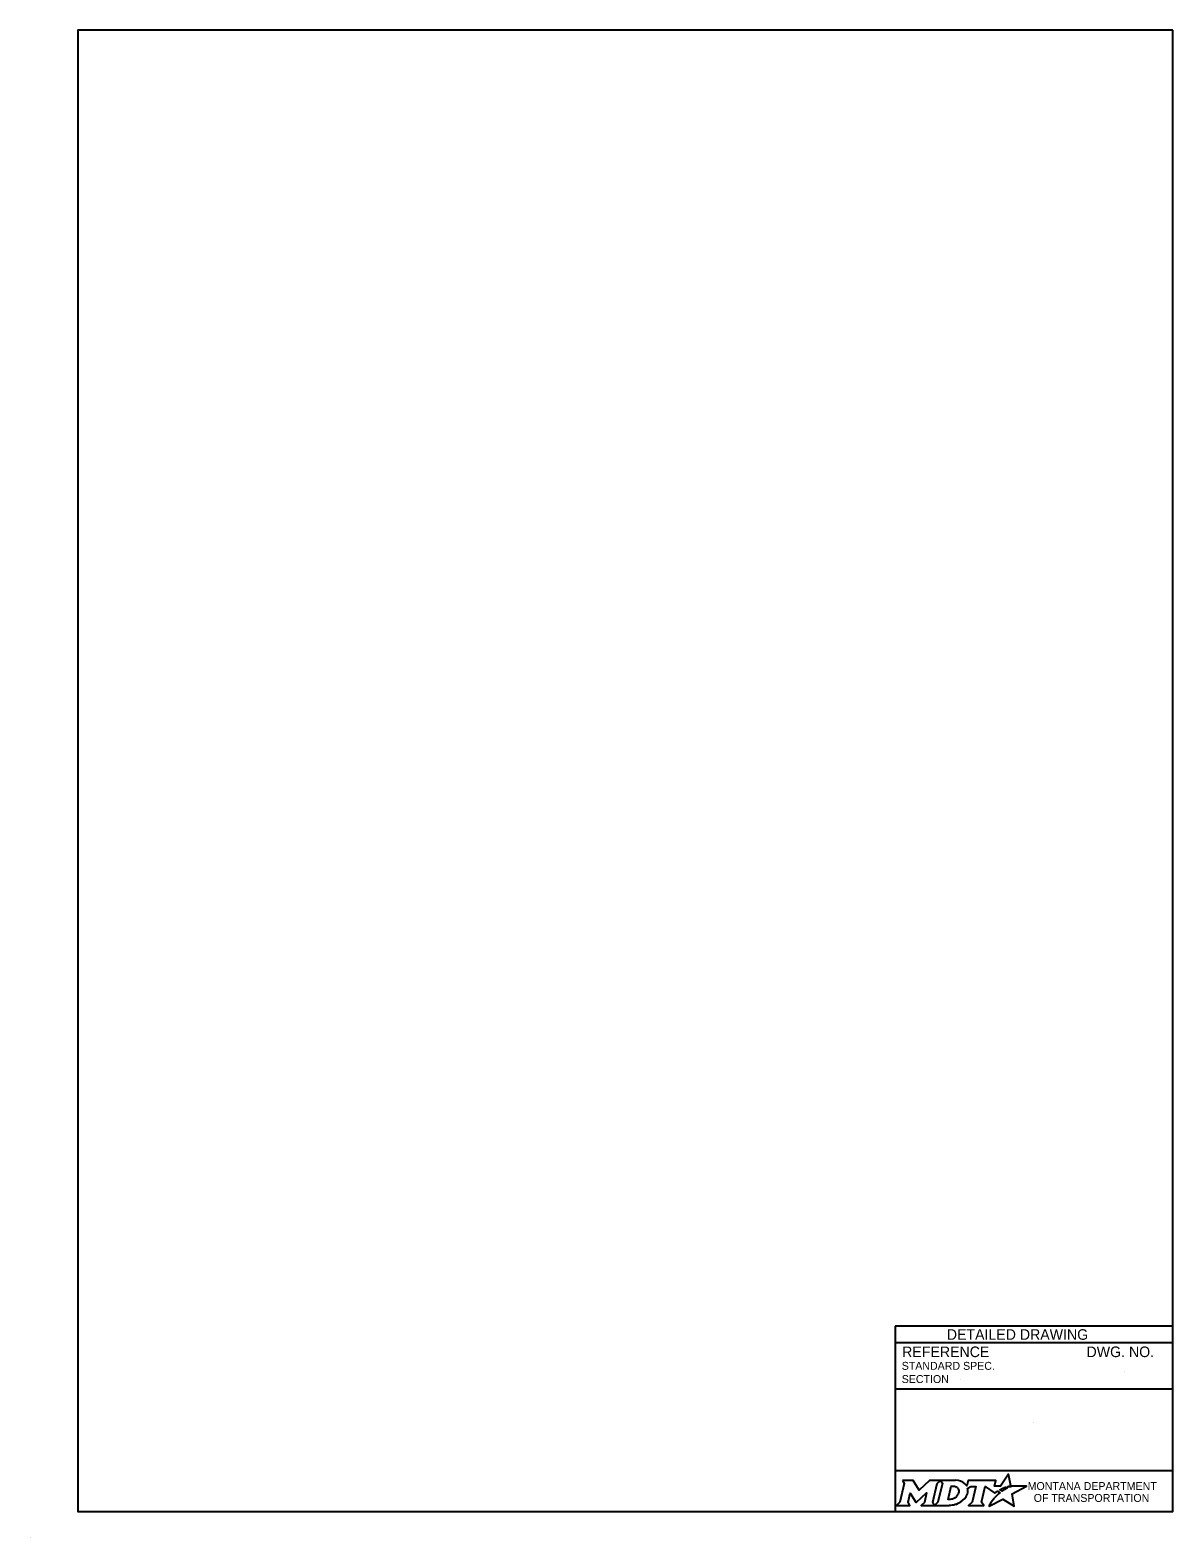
# Model space of a CAD drawing. Extents: x 49991.4 to 50047.6, y 49987.6 to 50011.4.
# Drawn here: x 49999.98 to 50008.61, y 49999.86 to 50011.26 of the extents above; entities that cross this region are included whole.
import ezdxf

# ---------------------------------------------------------------- set-up
doc = ezdxf.new("R2010")
doc.units = 0
doc.layers.add('Level 1', color=7, linetype='Continuous')
doc.layers.add('Level 2', color=7, linetype='Continuous')

msp = doc.modelspace()

# ---------------------------------------------------------------- linework, layer by layer
at = {"layer": 'Level 1'}
msp.add_line((49999.977, 49999.862), (49999.977, 49999.862), dxfattribs=at)
msp.add_lwpolyline([(50008.615, 50011.263), (50000.336, 50011.263), (50000.336, 50000.062), (50008.615, 50000.062)], close=True, dxfattribs=at)
at = {"layer": 'Level 2'}
for p, q in [((50008.615, 50001.462), (50006.515, 50001.462)), ((50006.515, 50001.462), (50006.515, 50000.062)), ((50008.615, 50001.337), (50006.515, 50001.337)), ((50007.009, 50001.063), (50007.009, 50001.063)), ((50008.251, 50001.122), (50008.251, 50001.122)), ((50008.615, 50000.987), (50006.515, 50000.987)), ((50007.565, 50000.738), (50007.565, 50000.738)), ((50008.615, 50000.369), (50006.515, 50000.369))]:
    msp.add_line(p, q, dxfattribs=at)
for points in [[(50007.377, 50000.245), (50007.367, 50000.25), (50007.378, 50000.253), (50007.39, 50000.255), (50007.373, 50000.345), (50007.313, 50000.254), (50007.266, 50000.253), (50007.276, 50000.297), (50007.067, 50000.297), (50007.057, 50000.255), (50007.051, 50000.263)], [(50006.57, 50000.297), (50006.584, 50000.274), (50006.551, 50000.131), (50006.525, 50000.108), (50006.627, 50000.108), (50006.613, 50000.131), (50006.629, 50000.201), (50006.673, 50000.132), (50006.678, 50000.132), (50006.753, 50000.202), (50006.737, 50000.13), (50006.712, 50000.108), (50006.814, 50000.108), (50006.8, 50000.132), (50006.833, 50000.274)], [(50006.833, 50000.274), (50006.859, 50000.297), (50006.776, 50000.297), (50006.697, 50000.224), (50006.652, 50000.297), (50006.57, 50000.297)], [(50006.972, 50000.297), (50006.859, 50000.297), (50006.873, 50000.275), (50006.839, 50000.131), (50006.814, 50000.108), (50006.925, 50000.108)], [(50006.996, 50000.211), (50006.995, 50000.203), (50006.992, 50000.193), (50006.988, 50000.185), (50006.982, 50000.178), (50006.976, 50000.171), (50006.968, 50000.164), (50006.959, 50000.16), (50006.95, 50000.156), (50006.941, 50000.154), (50006.932, 50000.153), (50006.916, 50000.153), (50006.94, 50000.253), (50006.956, 50000.253), (50006.963, 50000.252), (50006.971, 50000.25), (50006.977, 50000.247), (50006.983, 50000.243), (50006.988, 50000.238), (50006.992, 50000.232), (50006.995, 50000.226), (50006.996, 50000.218), (50006.996, 50000.215), (50006.996, 50000.211)], [(50007.064, 50000.238), (50007.088, 50000.251), (50007.125, 50000.251), (50007.097, 50000.131), (50007.069, 50000.108), (50007.185, 50000.108), (50007.168, 50000.131), (50007.196, 50000.251), (50007.268, 50000.2), (50007.289, 50000.215), (50007.309, 50000.204)], [(50007.253, 50000.148), (50007.237, 50000.124), (50007.233, 50000.116), (50007.227, 50000.107), (50007.225, 50000.103), (50007.33, 50000.156), (50007.414, 50000.101), (50007.401, 50000.194), (50007.508, 50000.252), (50007.458, 50000.253), (50007.428, 50000.253), (50007.407, 50000.254), (50007.401, 50000.252), (50007.396, 50000.251), (50007.387, 50000.249), (50007.377, 50000.245)], [(50007.327, 50000.217), (50007.324, 50000.215), (50007.306, 50000.225), (50007.316, 50000.231), (50007.32, 50000.233), (50007.329, 50000.237), (50007.335, 50000.239), (50007.343, 50000.243), (50007.35, 50000.245), (50007.362, 50000.238), (50007.358, 50000.236), (50007.353, 50000.233), (50007.349, 50000.231), (50007.344, 50000.228), (50007.342, 50000.227), (50007.339, 50000.225), (50007.337, 50000.224), (50007.334, 50000.222), (50007.332, 50000.221), (50007.329, 50000.219), (50007.327, 50000.217)], [(50006.97, 50000.116), (50006.979, 50000.118), (50006.992, 50000.124), (50007.012, 50000.135)], [(50007.267, 50000.164), (50007.267, 50000.164)]]:
    msp.add_lwpolyline(points, dxfattribs=at)
for centre, radius, start, end in [((50006.995, 50000.219), 0.0709, 339.5329, 15.8582), ((50006.951, 50000.236), 0.118, 300.9103, 339.1383)]:
    msp.add_arc(centre, radius, start, end, dxfattribs=at)
for centre, major_axis, ratio, start_param, end_param in [((50006.97, 50000.25), (0.0834, -0.0037), 0.568097, 0.61298, 1.570796), ((50007.026, 50000.257), (0.0361, -0.0295), 0.469099, 1.225588, 1.570796), ((50006.925, 50000.257), (0, 0.148), 0.987302, 3.139398, 3.456847), ((50007.26, 50000.156), (-0.00694, -0.00806), 0.008222, 0, 3.137361), ((50007.276, 50000.174), (-0.0098, -0.0102), 0.016458, 3.141593, 6.279097), ((50007.297, 50000.194), (-0.0112, -0.0097), 0.021651, 3.157348, 6.283185)]:
    msp.add_ellipse(centre, major_axis=major_axis, ratio=ratio, start_param=start_param, end_param=end_param, dxfattribs=at)

# ---------------------------------------------------------------- texts
for s, height, p in [('DETAILED DRAWING', 0.0799, (50006.906, 50001.36)), ('REFERENCE', 0.08, (50006.568, 50001.229)), ('DWG. NO.', 0.08, (50007.962, 50001.229)), ('STANDARD SPEC.', 0.06, (50006.565, 50001.133)), ('SECTION', 0.06, (50006.565, 50001.033))]:
    msp.add_text(s, height=height, dxfattribs=at).set_placement(p)
for s, p in [('MONTANA DEPARTMENT', (50007.517, 50000.224)), ('OF TRANSPORTATION', (50007.563, 50000.134))]:
    msp.add_text(s, height=0.06, rotation=360, dxfattribs=at).set_placement(p)

doc.saveas('drawing.dxf')
